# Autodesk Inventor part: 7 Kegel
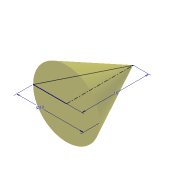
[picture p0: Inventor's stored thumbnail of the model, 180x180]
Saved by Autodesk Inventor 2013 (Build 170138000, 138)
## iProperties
Created: 2012-10
Part Number: 7 Kegel
Material: Allgemein
Vendor: www.inventor-faq.de
Document SubType Name: Modeling
Designer: Administrator
Manufacturer: www.inventor-faq.de
Density: 1 g/cm^3
RuleStatus: InUse
AfterDocOpen0: inventorfaq
BeforeDocSave0: inventorfaq
Author: Administrator
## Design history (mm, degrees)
sketch "Skizze1"
  geometry: L1 (0, 0)-(0, 10); L2 (0, 10)-(-5, 0); L3 (-5, 0)-(0, 0)
  constraints: 6 end point, 1 perpendicular, 1 vertical
  dimensions: "d0" = 10 distance of L1.start L1.end; "d1" = 10 diameter of L2.end L1
revolve "Umdrehung1" sketch "Skizze1" stored, may be unused: angle "d2" = 90 deg
node "Volumenkörper1"
